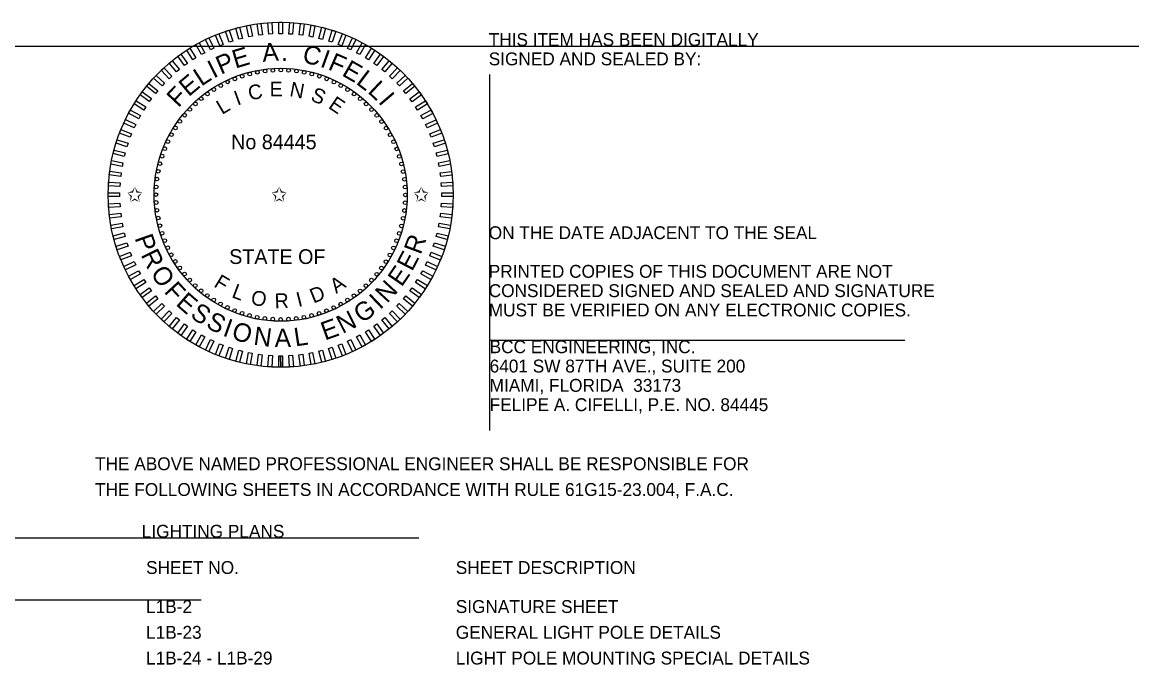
# Model space of a CAD drawing. Extents: x -811.2 to -795, y -2307.6 to -2235.1.
# Drawn here: x -802.94 to -796.87, y -2238.99 to -2235.5 of the extents above; entities that cross this region are included whole.
import ezdxf

# ---------------------------------------------------------------- set-up
doc = ezdxf.new("R2010")
doc.units = 0
for name, color, linetype in [('AdhocPoint_dp', 7, 'Continuous'), ('Logo_dp', 7, 'Continuous'), ('TeleMisc', 7, 'Continuous'), ('TextDetails', 7, 'Continuous'), ('TextMisc', 7, 'Continuous')]:
    doc.layers.add(name, color=color, linetype=linetype)

msp = doc.modelspace()

# ---------------------------------------------------------------- linework, layer by layer
at = {"layer": 'AdhocPoint_dp'}
for p, q in [((-808.3596, -2235.6292), (-796.8708, -2235.6292)), ((-800.3974, -2235.7843), (-800.3974, -2237.719)), ((-800.3974, -2237.229), (-798.1407, -2237.229)), ((-809.3854, -2238.3022), (-800.7818, -2238.3022)), ((-801.9648, -2238.6414), (-810.4432, -2238.6414))]:
    msp.add_line(p, q, dxfattribs=at)
at = {"layer": 'TextDetails'}
for radius in [0.9375, 0.6875]:
    msp.add_circle((-801.5329, -2236.4379), radius, dxfattribs=at)
at = {"layer": 'TextMisc'}
for p, q in [((-801.5429, -2237.3754), (-801.5431, -2237.3129)), ((-801.5329, -2237.3754), (-801.5331, -2237.3129)), ((-801.5229, -2237.3754), (-801.5231, -2237.3129))]:
    msp.add_line(p, q, dxfattribs=at)
for points in [[(-801.6869, -2235.5764), (-801.7067, -2235.5802), (-801.7184, -2235.5189), (-801.6986, -2235.5151)], [(-801.6325, -2235.5685), (-801.6525, -2235.571), (-801.6603, -2235.5091), (-801.6403, -2235.5065)], [(-801.5777, -2235.5639), (-801.5978, -2235.5652), (-801.6018, -2235.5029), (-801.5816, -2235.5016)], [(-801.5227, -2235.5629), (-801.5429, -2235.5629), (-801.5429, -2235.5004), (-801.5227, -2235.5004)], [(-801.4678, -2235.5652), (-801.488, -2235.564), (-801.484, -2235.5016), (-801.4639, -2235.5029)], [(-801.4131, -2235.571), (-801.4332, -2235.5685), (-801.4254, -2235.5066), (-801.4053, -2235.5091)], [(-801.359, -2235.5803), (-801.3788, -2235.5765), (-801.3671, -2235.5152), (-801.3473, -2235.5189)], [(-801.8456, -2235.6206), (-801.8643, -2235.628), (-801.8873, -2235.5699), (-801.8686, -2235.5625)], [(-801.7936, -2235.6025), (-801.8128, -2235.6088), (-801.8321, -2235.5494), (-801.8129, -2235.5432)], [(-801.7407, -2235.5878), (-801.7602, -2235.5928), (-801.7758, -2235.5324), (-801.7562, -2235.5273)], [(-801.3054, -2235.5929), (-801.325, -2235.5879), (-801.3095, -2235.5274), (-801.2899, -2235.5324)], [(-801.2528, -2235.6088), (-801.272, -2235.6026), (-801.2527, -2235.5432), (-801.2335, -2235.5494)], [(-801.2013, -2235.6281), (-801.2201, -2235.6206), (-801.1971, -2235.5626), (-801.1783, -2235.57)], [(-801.9455, -2235.6662), (-801.9632, -2235.6759), (-801.9933, -2235.6212), (-801.9756, -2235.6115)], [(-801.8963, -2235.6418), (-801.9145, -2235.6504), (-801.9411, -2235.5939), (-801.9229, -2235.5853)], [(-801.1511, -2235.6505), (-801.1694, -2235.6419), (-801.1428, -2235.5854), (-801.1246, -2235.594)], [(-801.1025, -2235.676), (-801.1201, -2235.6663), (-801.0901, -2235.6116), (-801.0724, -2235.6213)], [(-802.039, -2235.724), (-802.0553, -2235.7359), (-802.092, -2235.6853), (-802.0757, -2235.6735)], [(-801.9932, -2235.6936), (-802.0102, -2235.7044), (-802.0437, -2235.6517), (-802.0266, -2235.6409)], [(-801.0555, -2235.7045), (-801.0725, -2235.6937), (-801.039, -2235.641), (-801.022, -2235.6518)], [(-801.0104, -2235.736), (-801.0267, -2235.7241), (-800.99, -2235.6736), (-800.9737, -2235.6854)], [(-802.1245, -2235.793), (-802.1392, -2235.8069), (-802.182, -2235.7613), (-802.1672, -2235.7475)], [(-802.0828, -2235.7572), (-802.0984, -2235.77), (-802.1382, -2235.7219), (-802.1226, -2235.7091)], [(-800.9673, -2235.7702), (-800.9829, -2235.7573), (-800.9431, -2235.7092), (-800.9275, -2235.722)], [(-800.9265, -2235.807), (-800.9412, -2235.7932), (-800.8985, -2235.7477), (-800.8838, -2235.7615)], [(-802.1638, -2235.8315), (-802.1776, -2235.8462), (-802.2232, -2235.8034), (-802.2093, -2235.7887)], [(-800.8881, -2235.8463), (-800.9019, -2235.8316), (-800.8564, -2235.7889), (-800.8426, -2235.8036)], [(-802.2349, -2235.9153), (-802.2467, -2235.9316), (-802.2972, -2235.8949), (-802.2854, -2235.8786)], [(-802.2007, -2235.8723), (-802.2135, -2235.8878), (-802.2616, -2235.848), (-802.2488, -2235.8325)], [(-800.8522, -2235.888), (-800.8651, -2235.8724), (-800.817, -2235.8326), (-800.8041, -2235.8482)], [(-800.819, -2235.9318), (-800.8309, -2235.9155), (-800.7804, -2235.8788), (-800.7685, -2235.8951)], [(-802.2663, -2235.9604), (-802.2771, -2235.9775), (-802.3298, -2235.944), (-802.319, -2235.927)], [(-800.7887, -2235.9776), (-800.7995, -2235.9606), (-800.7468, -2235.9271), (-800.7359, -2235.9442)], [(-802.2948, -2236.0074), (-802.3045, -2236.0251), (-802.3593, -2235.995), (-802.3495, -2235.9773)], [(-800.7612, -2236.0253), (-800.7709, -2236.0076), (-800.7162, -2235.9775), (-800.7065, -2235.9952)], [(-802.3203, -2236.0561), (-802.3289, -2236.0744), (-802.3854, -2236.0478), (-802.3768, -2236.0295)], [(-800.7368, -2236.0745), (-800.7454, -2236.0563), (-800.6889, -2236.0297), (-800.6803, -2236.048)], [(-802.3428, -2236.1063), (-802.3502, -2236.1251), (-802.4082, -2236.1021), (-802.4008, -2236.0833)], [(-800.7156, -2236.1252), (-800.723, -2236.1065), (-800.665, -2236.0835), (-800.6575, -2236.1023)], [(-802.362, -2236.1578), (-802.3682, -2236.177), (-802.4276, -2236.1577), (-802.4214, -2236.1385)], [(-800.6976, -2236.1772), (-800.7038, -2236.158), (-800.6444, -2236.1387), (-800.6382, -2236.1579)], [(-802.3779, -2236.2104), (-802.383, -2236.23), (-802.4434, -2236.2144), (-802.4384, -2236.1949)], [(-800.6829, -2236.2301), (-800.6879, -2236.2106), (-800.6274, -2236.1951), (-800.6224, -2236.2146)], [(-802.3905, -2236.2639), (-802.3943, -2236.2837), (-802.4557, -2236.272), (-802.4519, -2236.2522)], [(-800.6715, -2236.2839), (-800.6753, -2236.2641), (-800.6139, -2236.2524), (-800.6102, -2236.2722)], [(-802.3998, -2236.3181), (-802.4023, -2236.3381), (-802.4643, -2236.3303), (-802.4617, -2236.3103)], [(-800.6635, -2236.3383), (-800.666, -2236.3183), (-800.6041, -2236.3105), (-800.6016, -2236.3305)], [(-802.4056, -2236.3728), (-802.4069, -2236.3929), (-802.4692, -2236.389), (-802.4679, -2236.3689)], [(-800.659, -2236.3931), (-800.6603, -2236.373), (-800.5979, -2236.369), (-800.5967, -2236.3892)], [(-802.408, -2236.4277), (-802.408, -2236.4479), (-802.4704, -2236.4479), (-802.4704, -2236.4277)], [(-802.4069, -2236.4827), (-802.4056, -2236.5028), (-802.4679, -2236.5067), (-802.4692, -2236.4866)], [(-800.6603, -2236.503), (-800.659, -2236.4829), (-800.5967, -2236.4868), (-800.5979, -2236.5069)], [(-800.6579, -2236.4481), (-800.6579, -2236.4279), (-800.5955, -2236.4279), (-800.5955, -2236.4481)], [(-802.4023, -2236.5375), (-802.3998, -2236.5575), (-802.4618, -2236.5653), (-802.4643, -2236.5453)], [(-800.6661, -2236.5577), (-800.6635, -2236.5376), (-800.6016, -2236.5455), (-800.6041, -2236.5655)], [(-802.3944, -2236.5918), (-802.3906, -2236.6117), (-802.4519, -2236.6234), (-802.4557, -2236.6035)], [(-800.6753, -2236.6119), (-800.6715, -2236.592), (-800.6102, -2236.6037), (-800.614, -2236.6236)], [(-802.383, -2236.6456), (-802.378, -2236.6652), (-802.4385, -2236.6807), (-802.4435, -2236.6612)], [(-800.6879, -2236.6654), (-800.6829, -2236.6458), (-800.6224, -2236.6613), (-800.6274, -2236.6809)], [(-802.3683, -2236.6986), (-802.362, -2236.7178), (-802.4214, -2236.7371), (-802.4277, -2236.7179)], [(-800.7039, -2236.718), (-800.6976, -2236.6988), (-800.6382, -2236.7181), (-800.6445, -2236.7373)], [(-802.3503, -2236.7505), (-802.3428, -2236.7693), (-802.4009, -2236.7923), (-802.4083, -2236.7735)], [(-800.7231, -2236.7695), (-800.7157, -2236.7507), (-800.6576, -2236.7737), (-800.665, -2236.7925)], [(-802.329, -2236.8012), (-802.3204, -2236.8195), (-802.3769, -2236.8461), (-802.3855, -2236.8278)], [(-802.3046, -2236.8505), (-802.2949, -2236.8682), (-802.3496, -2236.8983), (-802.3593, -2236.8806)], [(-800.7455, -2236.8197), (-800.7369, -2236.8014), (-800.6804, -2236.828), (-800.689, -2236.8463)], [(-802.2772, -2236.8982), (-802.2664, -2236.9152), (-802.3191, -2236.9487), (-802.3299, -2236.9316)], [(-800.7996, -2236.9154), (-800.7888, -2236.8983), (-800.736, -2236.9318), (-800.7469, -2236.9488)], [(-800.771, -2236.8684), (-800.7613, -2236.8507), (-800.7066, -2236.8808), (-800.7163, -2236.8984)], [(-802.2468, -2236.944), (-802.235, -2236.9603), (-802.2855, -2236.997), (-802.2973, -2236.9807)], [(-800.831, -2236.9605), (-800.8191, -2236.9441), (-800.7686, -2236.9808), (-800.7805, -2236.9972)], [(-802.2136, -2236.9878), (-802.2008, -2237.0034), (-802.2489, -2237.0432), (-802.2618, -2237.0276)], [(-802.1778, -2237.0295), (-802.1639, -2237.0442), (-802.2095, -2237.0869), (-802.2233, -2237.0722)], [(-800.902, -2237.0443), (-800.8882, -2237.0296), (-800.8427, -2237.0723), (-800.8565, -2237.0871)], [(-800.8652, -2237.0035), (-800.8523, -2236.9879), (-800.8042, -2237.0278), (-800.8171, -2237.0433)], [(-802.1394, -2237.0688), (-802.1246, -2237.0826), (-802.1674, -2237.1281), (-802.1821, -2237.1143)], [(-800.9414, -2237.0827), (-800.9266, -2237.0689), (-800.8839, -2237.1144), (-800.8986, -2237.1282)], [(-802.0985, -2237.1056), (-802.083, -2237.1185), (-802.1228, -2237.1666), (-802.1383, -2237.1537)], [(-802.0555, -2237.1398), (-802.0392, -2237.1517), (-802.0759, -2237.2022), (-802.0922, -2237.1903)], [(-801.0268, -2237.1518), (-801.0105, -2237.1399), (-800.9738, -2237.1904), (-800.9901, -2237.2023)], [(-800.983, -2237.1186), (-800.9675, -2237.1057), (-800.9277, -2237.1538), (-800.9432, -2237.1667)], [(-802.0104, -2237.1712), (-801.9933, -2237.1821), (-802.0268, -2237.2348), (-802.0438, -2237.224)], [(-801.9634, -2237.1998), (-801.9457, -2237.2095), (-801.9758, -2237.2642), (-801.9935, -2237.2545)], [(-801.1203, -2237.2096), (-801.1026, -2237.1999), (-801.0725, -2237.2546), (-801.0902, -2237.2643)], [(-801.0727, -2237.1822), (-801.0556, -2237.1713), (-801.0222, -2237.2241), (-801.0392, -2237.2349)], [(-801.9147, -2237.2253), (-801.8964, -2237.2339), (-801.923, -2237.2904), (-801.9413, -2237.2818)], [(-801.8645, -2237.2477), (-801.8457, -2237.2552), (-801.8687, -2237.3132), (-801.8875, -2237.3058)], [(-801.813, -2237.2669), (-801.7938, -2237.2732), (-801.8131, -2237.3326), (-801.8323, -2237.3263)], [(-801.2722, -2237.2732), (-801.253, -2237.267), (-801.2337, -2237.3264), (-801.2529, -2237.3326)], [(-801.2203, -2237.2552), (-801.2015, -2237.2478), (-801.1785, -2237.3058), (-801.1973, -2237.3133)], [(-801.1696, -2237.234), (-801.1513, -2237.2254), (-801.1247, -2237.2819), (-801.143, -2237.2905)], [(-801.7604, -2237.2829), (-801.7409, -2237.2879), (-801.7564, -2237.3484), (-801.7759, -2237.3434)], [(-801.7069, -2237.2955), (-801.6871, -2237.2993), (-801.6988, -2237.3606), (-801.7186, -2237.3568)], [(-801.6527, -2237.3047), (-801.6327, -2237.3073), (-801.6405, -2237.3692), (-801.6605, -2237.3667)], [(-801.598, -2237.3106), (-801.5779, -2237.3118), (-801.5818, -2237.3741), (-801.602, -2237.3729)], [(-801.5431, -2237.3129), (-801.5229, -2237.3129), (-801.5229, -2237.3754), (-801.5431, -2237.3754)], [(-801.4881, -2237.3118), (-801.468, -2237.3106), (-801.4641, -2237.3729), (-801.4842, -2237.3741)], [(-801.4334, -2237.3073), (-801.4133, -2237.3048), (-801.4055, -2237.3667), (-801.4255, -2237.3692)], [(-801.379, -2237.2993), (-801.3591, -2237.2955), (-801.3474, -2237.3569), (-801.3673, -2237.3607)], [(-801.3252, -2237.288), (-801.3056, -2237.2829), (-801.2901, -2237.3434), (-801.3097, -2237.3484)]]:
    msp.add_lwpolyline(points, close=True, dxfattribs=at)
for centre in [(-801.6173, -2235.7657), (-801.5749, -2235.7617), (-801.5324, -2235.7604), (-801.4898, -2235.7618), (-801.4475, -2235.7658), (-801.8209, -2235.8247), (-801.7818, -2235.8078), (-801.7417, -2235.7934), (-801.7009, -2235.7816), (-801.6593, -2235.7723), (-801.4054, -2235.7725), (-801.3639, -2235.7818), (-801.323, -2235.7938), (-801.283, -2235.8082), (-801.244, -2235.8251), (-801.9307, -2235.8895), (-801.8955, -2235.8656), (-801.8588, -2235.8439), (-801.2061, -2235.8445), (-801.1694, -2235.8662), (-801.9963, -2235.9436), (-801.9643, -2235.9155), (-801.1343, -2235.8901), (-801.1007, -2235.9163), (-801.0688, -2235.9444), (-802.0546, -2236.0056), (-802.0264, -2235.9737), (-801.0387, -2235.9745), (-801.0106, -2236.0065), (-802.0807, -2236.0392), (-800.9845, -2236.0401), (-802.1263, -2236.111), (-802.1046, -2236.0744), (-800.9606, -2236.0754), (-800.939, -2236.112), (-802.1626, -2236.188), (-802.1457, -2236.1489), (-800.9197, -2236.1499), (-800.9028, -2236.189), (-802.1771, -2236.228), (-800.8884, -2236.2291), (-802.1983, -2236.3104), (-802.189, -2236.2689), (-800.8766, -2236.27), (-800.8674, -2236.3115), (-802.205, -2236.3524), (-800.8607, -2236.3535), (-802.209, -2236.3948), (-800.8568, -2236.3959), (-802.2104, -2236.4373), (-802.2091, -2236.4799), (-800.8568, -2236.481), (-800.8555, -2236.4385), (-802.2051, -2236.5222), (-800.8609, -2236.5234), (-802.1985, -2236.5643), (-802.1893, -2236.6058), (-800.8769, -2236.6069), (-800.8676, -2236.5654), (-802.1774, -2236.6467), (-800.8888, -2236.6478), (-802.163, -2236.6868), (-802.1462, -2236.7258), (-800.9202, -2236.7269), (-800.9032, -2236.6878), (-802.1269, -2236.7638), (-800.9395, -2236.7648), (-802.1052, -2236.8004), (-802.0813, -2236.8356), (-800.9852, -2236.8366), (-800.9612, -2236.8014), (-802.0553, -2236.8693), (-802.0272, -2236.9012), (-801.0395, -2236.9021), (-801.0113, -2236.8702), (-801.9971, -2236.9314), (-801.9652, -2236.9595), (-801.1015, -2236.9602), (-801.0696, -2236.9321), (-801.9316, -2236.9856), (-801.8964, -2237.0096), (-801.8598, -2237.0313), (-801.207, -2237.0318), (-801.1704, -2237.0102), (-801.1352, -2236.9863), (-801.8219, -2237.0506), (-801.7828, -2237.0676), (-801.7428, -2237.082), (-801.702, -2237.0939), (-801.365, -2237.0942), (-801.3241, -2237.0824), (-801.2841, -2237.068), (-801.245, -2237.0511), (-801.6604, -2237.1033), (-801.6184, -2237.1099), (-801.576, -2237.114), (-801.5329, -2237.1154), (-801.4909, -2237.1141), (-801.4486, -2237.1101), (-801.4065, -2237.1035)]:
    msp.add_circle(centre, 0.01, dxfattribs=at)

# ---------------------------------------------------------------- texts
at = {"layer": 'Logo_dp'}
for s, p in [('THIS ITEM HAS BEEN DIGITALLY', (-800.4024, -2235.6292)), ('SIGNED AND SEALED BY:', (-800.4024, -2235.7342)), ('ON THE DATE ADJACENT TO THE SEAL', (-800.4024, -2236.6792)), ('PRINTED COPIES OF THIS DOCUMENT ARE NOT ', (-800.4024, -2236.8892)), ('CONSIDERED SIGNED AND SEALED AND SIGNATURE ', (-800.4024, -2236.9942)), ('MUST BE VERIFIED ON ANY ELECTRONIC COPIES.', (-800.4024, -2237.0992)), ('BCC ENGINEERING, INC.', (-800.3974, -2237.299)), ('6401 SW 87TH AVE., SUITE 200', (-800.3974, -2237.404)), ('MIAMI, FLORIDA  33173', (-800.3974, -2237.509)), ('FELIPE A. CIFELLI, P.E. NO. 84445', (-800.3974, -2237.614)), ('THE ABOVE NAMED PROFESSIONAL ENGINEER SHALL BE RESPONSIBLE FOR ', (-802.5415, -2237.9352)), ('THE FOLLOWING SHEETS IN ACCORDANCE WITH RULE 61G15-23.004, F.A.C.', (-802.5415, -2238.0752)), ('LIGHTING PLANS', (-802.2878, -2238.3022))]:
    msp.add_text(s, height=0.07, dxfattribs=at).set_placement(p)
at = {"layer": 'TeleMisc'}
for s, p in [('SHEET NO.', (-802.2643, -2238.4992)), ('SHEET DESCRIPTION', (-800.5815, -2238.4992)), ('L1B-2', (-802.2643, -2238.7114)), ('SIGNATURE SHEET', (-800.5815, -2238.7114)), ('L1B-23', (-802.2643, -2238.8514)), ('GENERAL LIGHT POLE DETAILS', (-800.5815, -2238.8514)), ('L1B-24 - L1B-29', (-802.2643, -2238.9914)), ('LIGHT POLE MOUNTING SPECIAL DETAILS', (-800.5815, -2238.9914))]:
    msp.add_text(s, height=0.07, dxfattribs=at).set_placement(p)
at = {"layer": 'TextMisc'}
for s, height, rotation, p in [('E', 0.1, 16.54261, (-801.7793, -2235.7522)), ('A', 0.1, 4.42103, (-801.6298, -2235.7157)), ('C', 0.1, 347.7999, (-801.4192, -2235.7182)), ('P', 0.1, 23.28287, (-801.8581, -2235.7858)), ('.', 0.1, 356.65403, (-801.5313, -2235.7092)), ('I', 0.1, 340.0631, (-801.3234, -2235.74)), ('F', 0.1, 336.52991, (-801.2807, -2235.7543)), ('L', 0.1, 33.07918, (-801.9643, -2235.8507)), ('I', 0.1, 26.81606, (-801.8977, -2235.8071)), ('E', 0.1, 330.07956, (-801.2055, -2235.7869)), ('L', 0.1, 323.03732, (-801.1282, -2235.832)), ('E', 0.1, 40.12142, (-802.033, -2235.908)), ('L', 0.1, 316.7742, (-801.0645, -2235.8797)), ('F', 0.1, 46.57177, (-802.0894, -2235.9675)), ('I', 0.08, 20.01168, (-801.7686, -2235.9538)), ('C', 0.08, 12.20255, (-801.7007, -2235.9263)), ('E', 0.08, 0.41861, (-801.5926, -2235.9028)), ('N', 0.08, 349.29143, (-801.4883, -2235.9013)), ('S', 0.08, 337.02207, (-801.3753, -2235.9231)), ('I', 0.1, 310.51108, (-801.0064, -2235.9342)), ('L', 0.08, 30.40215, (-801.8521, -2236.0043)), ('E', 0.08, 325.86633, (-801.2786, -2235.9633)), ('P', 0.1, 289.40551, (-802.3276, -2236.6725)), ('R', 0.1, 69.5134, (-800.7727, -2236.7676)), ('R', 0.1, 296.14576, (-802.2946, -2236.7641)), ('E', 0.1, 62.47116, (-800.8189, -2236.8583)), ('O', 0.1, 303.96711, (-802.2431, -2236.8647)), ('E', 0.1, 55.42892, (-800.8758, -2236.9427)), ('F', 0.1, 312.62798, (-802.1708, -2236.9668)), ('F', 0.08, 328.72408, (-801.901, -2236.9345)), ('A', 0.08, 34.49917, (-801.2311, -2236.9773)), ('N', 0.1, 47.17876, (-800.9551, -2237.0317)), ('E', 0.1, 319.07833, (-802.1073, -2237.0351)), ('L', 0.08, 339.29159, (-801.8037, -2236.9936)), ('O', 0.08, 349.68206, (-801.699, -2237.0333)), ('I', 0.08, 14.20366, (-801.4369, -2237.0485)), ('D', 0.08, 22.01279, (-801.3549, -2237.0298)), ('R', 0.08, 2.33977, (-801.5645, -2237.0552)), ('G', 0.1, 35.11153, (-801.092, -2237.1394)), ('I', 0.1, 43.64556, (-800.9928, -2237.0662)), ('S', 0.1, 326.12056, (-802.0297, -2237.101)), ('S', 0.1, 333.193, (-801.9443, -2237.1572)), ('N', 0.1, 26.86136, (-801.1972, -2237.1954)), ('I', 0.1, 340.26543, (-801.8526, -2237.2023)), ('O', 0.1, 343.79863, (-801.8049, -2237.2206)), ('E', 0.1, 19.81912, (-801.2926, -2237.2309)), ('N', 0.1, 352.45949, (-801.6839, -2237.2526)), ('A', 0.1, 0.70966, (-801.5655, -2237.2659)), ('L', 0.1, 8.47665, (-801.4533, -2237.2627))]:
    msp.add_text(s, height=height, rotation=rotation, dxfattribs=at).set_placement(p)
for s, p in [('No 84445', (-801.8019, -2236.1907)), ('✩', (-802.3679, -2236.4758)), ('✩', (-801.5832, -2236.4758)), ('✩', (-800.8113, -2236.4758)), ('STATE OF', (-801.8126, -2236.8141))]:
    msp.add_text(s, height=0.08, dxfattribs=at).set_placement(p)

doc.saveas('drawing.dxf')
